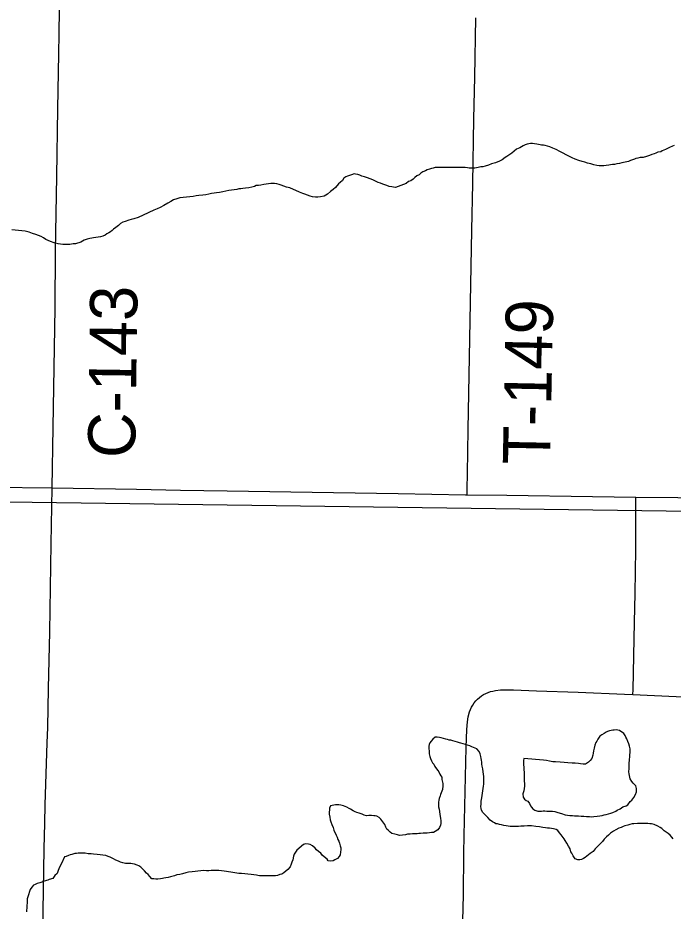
# Model space of a CAD drawing. Extents: x 2.1 to 73.9, y 4 to 26.
# Drawn here: x 46.07 to 46.463, y 19.554 to 20.091 of the extents above; entities that cross this region are included whole.
import ezdxf

# ---------------------------------------------------------------- set-up
doc = ezdxf.new("R2010")
doc.units = 0
for name, color, linetype in [('GM_X_County_Road', 7, 'Continuous'), ('GM_X_County_Road_Text', 7, 'Continuous'), ('GM_X_Minor_Lake', 7, 'Continuous'), ('GM_X_Minor_River', 7, 'Continuous'), ('GM_X_State_Route', 7, 'Continuous'), ('GM_X_Township_Road', 7, 'Continuous'), ('GM_X_Township_Road_Text', 7, 'Continuous')]:
    doc.layers.add(name, color=color, linetype=linetype)

msp = doc.modelspace()

# ---------------------------------------------------------------- linework, layer by layer
at = {"layer": 'GM_X_County_Road'}
for points in [[(46.09468, 20.06932), (46.0949, 20.08134), (46.09523, 20.11081), (46.09615, 20.14974), (46.09689, 20.1833)], [(46.09063, 19.80873), (46.09126, 19.84507), (46.09233, 19.91657), (46.09258, 19.95078), (46.09351, 19.99585), (46.09409, 20.03627), (46.09468, 20.06932)], [(46.33705, 19.54086), (46.33751, 19.56417), (46.33781, 19.58903), (46.33795, 19.5999), (46.33857, 19.6263), (46.33907, 19.65272), (46.33953, 19.66357), (46.33992, 19.66818), (46.34042, 19.6712), (46.34124, 19.67414), (46.34179, 19.67556), (46.34243, 19.67694), (46.34316, 19.67826), (46.344, 19.67953), (46.34494, 19.68071), (46.34598, 19.68182), (46.3471, 19.68283), (46.34831, 19.68374), (46.34959, 19.68453), (46.35095, 19.68521), (46.35235, 19.68581), (46.35379, 19.6863), (46.35526, 19.68669), (46.35675, 19.68699), (46.3598, 19.68735), (46.36287, 19.68749), (46.36751, 19.68747), (46.38148, 19.68688), (46.40633, 19.68595), (46.43427, 19.68478), (46.43929, 19.68457)], [(46.43929, 19.68457), (46.46532, 19.68344), (46.49326, 19.68214), (46.49798, 19.68199), (46.50147, 19.6819), (46.5063, 19.68176)]]:
    msp.add_lwpolyline(points, dxfattribs=at)
at = {"layer": 'GM_X_Minor_Lake'}
for points in [[(46.37385, 19.64611), (46.37366, 19.64497), (46.37366, 19.64364), (46.37366, 19.64231), (46.37384, 19.64098), (46.37402, 19.63642), (46.37402, 19.63262), (46.3742, 19.6311), (46.3742, 19.62958), (46.37381, 19.62673), (46.37324, 19.62483), (46.37343, 19.62293), (46.37418, 19.62178), (46.37513, 19.62083), (46.37627, 19.62045), (46.37722, 19.61911), (46.37779, 19.61778), (46.37836, 19.61683), (46.37912, 19.61588), (46.38044, 19.61511), (46.38216, 19.61454), (46.3833, 19.61454), (46.38444, 19.61453), (46.38539, 19.61472), (46.38634, 19.61472), (46.38767, 19.61452), (46.38938, 19.61452), (46.3909, 19.61451), (46.39242, 19.61432), (46.39413, 19.61374), (46.39641, 19.61317), (46.39869, 19.6124), (46.40135, 19.61201), (46.40307, 19.61182), (46.40421, 19.61181), (46.40535, 19.61181), (46.40668, 19.61162), (46.4082, 19.61161), (46.40972, 19.61142), (46.41143, 19.61141), (46.41314, 19.61122), (46.41428, 19.61121), (46.4158, 19.6114), (46.41789, 19.61158), (46.41942, 19.61177), (46.42075, 19.61196), (46.42208, 19.61233), (46.42322, 19.61252), (46.42607, 19.61327), (46.42722, 19.61365), (46.42893, 19.61459), (46.42988, 19.61516), (46.43159, 19.61592), (46.43331, 19.61705), (46.43521, 19.61781), (46.43616, 19.61837), (46.43769, 19.62027), (46.43864, 19.62103), (46.43978, 19.62273), (46.44074, 19.62444), (46.4415, 19.62615), (46.44151, 19.62805), (46.44094, 19.62976), (46.43942, 19.63129), (46.43866, 19.63224), (46.43771, 19.63395), (46.43734, 19.6349), (46.43715, 19.63586), (46.43696, 19.637), (46.43677, 19.63814), (46.43697, 19.64023), (46.43697, 19.64175), (46.43697, 19.64327), (46.43717, 19.64517), (46.43736, 19.64764), (46.43756, 19.65049), (46.43756, 19.65201), (46.43718, 19.65353), (46.43681, 19.65505), (46.43624, 19.65638), (46.43567, 19.6579), (46.4351, 19.65905), (46.43454, 19.66), (46.43378, 19.66114), (46.43112, 19.66305), (46.42922, 19.66343), (46.42808, 19.66325), (46.42713, 19.66325), (46.42522, 19.66269), (46.42408, 19.66231), (46.42313, 19.66193), (46.42199, 19.66118), (46.42066, 19.66042), (46.41932, 19.65947), (46.41818, 19.65777), (46.41761, 19.65663), (46.41703, 19.65568), (46.41646, 19.65416), (46.41608, 19.65245), (46.41569, 19.65074), (46.41531, 19.64941)], [(46.41531, 19.64941), (46.41512, 19.64808), (46.41454, 19.64618), (46.41359, 19.64486), (46.41264, 19.64391), (46.41073, 19.64277), (46.4094, 19.64278), (46.40788, 19.64297), (46.40655, 19.64317), (46.40465, 19.64336), (46.40275, 19.64337), (46.40028, 19.64356), (46.398, 19.64376), (46.39552, 19.64396), (46.39286, 19.64416), (46.39115, 19.64416), (46.38925, 19.64455), (46.38735, 19.64493), (46.38564, 19.64513), (46.37385, 19.64611)]]:
    msp.add_lwpolyline(points, dxfattribs=at)
at = {"layer": 'GM_X_Minor_River'}
for points in [[(46.45195, 20.00929), (46.45062, 20.00891), (46.44929, 20.00834), (46.44739, 20.00778), (46.44548, 20.00721), (46.44358, 20.00703), (46.44225, 20.00665), (46.44111, 20.00647), (46.44016, 20.00609), (46.43902, 20.00571), (46.43788, 20.00534), (46.43654, 20.00477), (46.43255, 20.00383), (46.43122, 20.00345), (46.4297, 20.00327), (46.42817, 20.00289), (46.42703, 20.0029), (46.42589, 20.00271), (46.42475, 20.00252), (46.42323, 20.00234), (46.42171, 20.00215), (46.42038, 20.00216), (46.41905, 20.00216), (46.41753, 20.00235), (46.41582, 20.00274), (46.41392, 20.00331), (46.41201, 20.0037), (46.4103, 20.00427), (46.40878, 20.00466), (46.40688, 20.00524), (46.4046, 20.00619), (46.40289, 20.00696), (46.40118, 20.00772), (46.39929, 20.00868), (46.39739, 20.00963), (46.3953, 20.01078), (46.39321, 20.01193), (46.39112, 20.01269), (46.38941, 20.01346), (46.38789, 20.01384), (46.38656, 20.01423), (46.38561, 20.01461), (46.38447, 20.01461), (46.38352, 20.01481), (46.38162, 20.01519), (46.38028, 20.01539), (46.37895, 20.01558), (46.37781, 20.01558), (46.37686, 20.0154), (46.37572, 20.01502), (46.37458, 20.01464), (46.37344, 20.01408), (46.3723, 20.01351), (46.37134, 20.01294), (46.37039, 20.01256), (46.36944, 20.01219), (46.36658, 20.00972), (46.36487, 20.00859), (46.36354, 20.00764), (46.36259, 20.00707), (46.36087, 20.00575), (46.35916, 20.00499), (46.35669, 20.00386), (46.3544, 20.0033), (46.3525, 20.00254), (46.3506, 20.00198), (46.34908, 20.0016), (46.34794, 20.00141), (46.34641, 20.00104), (46.34546, 20.00085), (46.34432, 20.00066), (46.34318, 20.00067), (46.34204, 20.00067), (46.3409, 20.00067), (46.33995, 20.00087), (46.33862, 20.00106), (46.33672, 20.00107), (46.3352, 20.00107), (46.33348, 20.00108), (46.33234, 20.00108), (46.33101, 20.00108), (46.32968, 20.00109), (46.32816, 20.00109), (46.32702, 20.00109), (46.32569, 20.0011), (46.32417, 20.0011), (46.32284, 20.00111), (46.32151, 20.00111), (46.32056, 20.00111), (46.31941, 20.00074), (46.31827, 20.00055), (46.31713, 20.00017), (46.3158, 19.9998), (46.31466, 19.99904), (46.31314, 19.99847), (46.31199, 19.99772), (46.31085, 19.99677), (46.30952, 19.99601), (46.30838, 19.99506), (46.30742, 19.99412), (46.3059, 19.99317)], [(46.46394, 20.01438), (46.46299, 20.01401), (46.46128, 20.01306), (46.46033, 20.01268), (46.4588, 20.01193), (46.45785, 20.01155), (46.4569, 20.01117), (46.45595, 20.01061), (46.45424, 20.01023), (46.4531, 20.00966), (46.45195, 20.00929)], [(46.3059, 19.99317), (46.30457, 19.99261), (46.30305, 19.99147), (46.29677, 19.98902), (46.29544, 19.98921), (46.29448, 19.9894), (46.29296, 19.98979), (46.29144, 19.99036), (46.28917, 19.99113), (46.28764, 19.9917), (46.28632, 19.99209), (46.28441, 19.99304), (46.28308, 19.99362), (46.28157, 19.99438), (46.27986, 19.99496), (46.27814, 19.99553), (46.27662, 19.99592), (46.2753, 19.99649), (46.27416, 19.99687), (46.27282, 19.99707), (46.27187, 19.99726), (46.27035, 19.9967), (46.26902, 19.99632), (46.26788, 19.99594), (46.26693, 19.99556), (46.26578, 19.99462), (46.26483, 19.99329), (46.2635, 19.99215), (46.26255, 19.9912), (46.26064, 19.98912), (46.25931, 19.98798), (46.25778, 19.98666), (46.25588, 19.98514), (46.25398, 19.98382), (46.25169, 19.98344), (46.25017, 19.98326), (46.24865, 19.98326), (46.24694, 19.98346), (46.24542, 19.98384), (46.2439, 19.98442), (46.24238, 19.98499), (46.24105, 19.98556), (46.23915, 19.98633), (46.23326, 19.98882), (46.23136, 19.98939), (46.22965, 19.98997), (46.22813, 19.99054), (46.2268, 19.99093), (46.22547, 19.99131), (46.22414, 19.9915), (46.223, 19.99151), (46.22186, 19.99151), (46.22053, 19.99133), (46.21919, 19.99114), (46.21767, 19.99095), (46.21596, 19.99058), (46.21444, 19.99039), (46.21311, 19.99021), (46.21216, 19.98964), (46.21044, 19.98926), (46.20873, 19.98889), (46.20664, 19.9887), (46.20512, 19.98852), (46.20379, 19.98833), (46.20265, 19.98834), (46.20151, 19.98796), (46.1998, 19.98777), (46.19827, 19.98759), (46.19675, 19.98721), (46.19485, 19.98684), (46.19314, 19.98646), (46.19105, 19.98609), (46.18933, 19.9859), (46.18781, 19.98572), (46.18629, 19.98553), (46.18458, 19.98516), (46.18287, 19.98478), (46.18116, 19.98441), (46.17868, 19.98422), (46.17716, 19.98404), (46.17526, 19.98366), (46.17336, 19.98348), (46.17127, 19.98329), (46.16917, 19.98311), (46.16727, 19.98292), (46.16537, 19.98236), (46.16347, 19.9816), (46.16176, 19.98066), (46.16004, 19.97971), (46.15757, 19.9782), (46.15547, 19.97707), (46.15357, 19.97631), (46.15167, 19.97555), (46.1452, 19.97253), (46.14215, 19.97102), (46.13968, 19.97027), (46.13797, 19.96989), (46.13664, 19.96952), (46.13435, 19.96876), (46.13302, 19.9682), (46.13169, 19.96744)], [(46.13169, 19.96744), (46.13035, 19.9663), (46.12883, 19.96498), (46.1275, 19.96403), (46.12655, 19.96327), (46.1256, 19.96252), (46.12464, 19.96195), (46.1235, 19.96119), (46.12236, 19.96043), (46.12103, 19.95987), (46.11969, 19.95949), (46.11817, 19.9593), (46.11684, 19.95912), (46.11551, 19.95893), (46.11437, 19.95875), (46.11323, 19.95837), (46.11171, 19.95799), (46.1098, 19.95743), (46.1079, 19.95629), (46.10467, 19.95535), (46.10314, 19.95517), (46.10219, 19.95498), (46.10124, 19.95479), (46.09991, 19.95479), (46.09839, 19.9548), (46.09706, 19.9548), (46.09554, 19.955), (46.09421, 19.95519), (46.09288, 19.95558), (46.09174, 19.95596), (46.08965, 19.95672), (46.08813, 19.9573), (46.0868, 19.95787), (46.08547, 19.95883), (46.08395, 19.95959), (46.08243, 19.96036), (46.08072, 19.96093), (46.07882, 19.96151), (46.07673, 19.96227), (46.07445, 19.96285), (46.06646, 19.96363)], [(45.71269, 19.80517), (46.5909, 19.79315)], [(46.36179, 19.60586), (46.36046, 19.60624), (46.35913, 19.60643), (46.35799, 19.60682), (46.35704, 19.60701), (46.35609, 19.60758), (46.35495, 19.60816), (46.35362, 19.60911), (46.35211, 19.61064), (46.35116, 19.61178), (46.35002, 19.61292), (46.34907, 19.61368), (46.34831, 19.61502), (46.34812, 19.61616), (46.34794, 19.6173), (46.34813, 19.61882), (46.34813, 19.62053), (46.34852, 19.62243), (46.34929, 19.62813), (46.34948, 19.62946), (46.34967, 19.63079), (46.34968, 19.6325), (46.34968, 19.63402), (46.34968, 19.63535), (46.3495, 19.63668), (46.34931, 19.6382), (46.34912, 19.63991), (46.34875, 19.64162), (46.34856, 19.64276), (46.34856, 19.6439), (46.34837, 19.64523), (46.34819, 19.64619), (46.348, 19.64733), (46.34762, 19.64904), (46.34705, 19.65037), (46.34553, 19.65189), (46.34364, 19.65285), (46.34249, 19.65323), (46.34136, 19.65381), (46.34003, 19.65419), (46.3387, 19.65458), (46.33737, 19.65496), (46.33603, 19.65534), (46.33508, 19.65554), (46.33394, 19.65592), (46.33261, 19.6563), (46.33109, 19.65669), (46.32995, 19.65707), (46.329, 19.65726), (46.32805, 19.65765), (46.32691, 19.65784), (46.32558, 19.65822), (46.32406, 19.65861), (46.32311, 19.6588), (46.32178, 19.659), (46.32064, 19.659), (46.31912, 19.65767), (46.31816, 19.65654), (46.3174, 19.65559), (46.31702, 19.65464), (46.31683, 19.6535), (46.31683, 19.65236), (46.31701, 19.65027), (46.31701, 19.64894), (46.31739, 19.64741), (46.31776, 19.64608), (46.31833, 19.64475), (46.3189, 19.64361), (46.31966, 19.64266), (46.32042, 19.64132), (46.32136, 19.63999), (46.32212, 19.63904), (46.32269, 19.63809), (46.32345, 19.63675), (46.32402, 19.6358), (46.32458, 19.63485), (46.32458, 19.63352), (46.32496, 19.632), (46.32515, 19.63105), (46.32514, 19.62972), (46.32495, 19.62763), (46.32457, 19.62649), (46.32419, 19.62554), (46.3238, 19.62459), (46.32361, 19.62364), (46.32304, 19.62212), (46.32285, 19.62117), (46.32265, 19.61984), (46.32265, 19.61832), (46.32265, 19.61718), (46.32302, 19.61566), (46.32321, 19.61433), (46.3234, 19.61243), (46.32378, 19.61034), (46.32396, 19.60863), (46.32396, 19.60711), (46.32377, 19.60616), (46.32319, 19.60464), (46.32205, 19.60331), (46.32053, 19.60237), (46.31957, 19.6018)], [(46.31957, 19.6018), (46.31843, 19.60161), (46.3171, 19.60142), (46.31577, 19.60124), (46.31444, 19.60124), (46.3133, 19.60125), (46.31178, 19.60106), (46.31083, 19.60106), (46.30969, 19.60088), (46.30855, 19.60088), (46.30702, 19.60088), (46.3055, 19.6007), (46.30398, 19.6007), (46.30265, 19.60033), (46.30094, 19.60014), (46.29923, 19.59996), (46.2979, 19.60034), (46.29638, 19.60072), (46.29448, 19.60111), (46.29353, 19.60187), (46.29258, 19.60283), (46.29163, 19.60378), (46.29087, 19.60492), (46.2903, 19.60644), (46.28803, 19.60968), (46.28689, 19.61063), (46.28556, 19.61159), (46.28461, 19.61178), (46.28366, 19.61178), (46.28233, 19.61198), (46.28081, 19.61198), (46.27928, 19.6118), (46.27795, 19.61218), (46.27682, 19.61275), (46.27491, 19.61333), (46.27359, 19.61371), (46.27245, 19.6141), (46.27131, 19.61467), (46.26979, 19.61562), (46.26884, 19.6162), (46.26751, 19.61696), (46.26656, 19.61734), (46.26542, 19.61773), (46.2639, 19.61811), (46.26276, 19.61831), (46.26181, 19.61831), (46.26067, 19.61831), (46.25971, 19.61812), (46.25876, 19.61794), (46.25781, 19.61775), (46.25705, 19.61642), (46.25705, 19.61528), (46.25685, 19.61395), (46.25685, 19.61262), (46.25723, 19.61091), (46.2576, 19.60939), (46.25798, 19.60806), (46.25855, 19.60653), (46.25931, 19.60463), (46.25968, 19.60311), (46.2612, 19.60007), (46.26177, 19.59892), (46.26214, 19.59759), (46.26271, 19.59645), (46.26309, 19.59531), (46.26347, 19.59379), (46.26385, 19.59246), (46.26384, 19.59151), (46.26365, 19.5898), (46.26346, 19.58828), (46.26288, 19.58733), (46.26193, 19.58619), (46.26041, 19.58524), (46.25927, 19.58468), (46.25774, 19.58449), (46.25622, 19.58469), (46.25565, 19.58564), (46.25395, 19.58716), (46.25281, 19.58812), (46.25186, 19.58926), (46.25053, 19.59021), (46.24939, 19.59136), (46.24844, 19.59231), (46.24692, 19.59365), (46.24541, 19.59441), (46.24446, 19.5946), (46.24274, 19.5948), (46.24141, 19.59442), (46.2376, 19.59101), (46.23665, 19.58987), (46.23589, 19.58874), (46.2355, 19.58741), (46.23512, 19.58532), (46.23455, 19.5838), (46.23416, 19.58266), (46.23359, 19.58114), (46.23207, 19.57944), (46.22978, 19.57754), (46.22845, 19.57678), (46.22731, 19.57641), (46.22597, 19.57584)], [(46.4635, 19.59796), (46.46255, 19.59891), (46.4616, 19.60005), (46.46046, 19.60101), (46.45914, 19.60196), (46.458, 19.60272), (46.45667, 19.60406), (46.45572, 19.60463), (46.4542, 19.60559), (46.45211, 19.60654), (46.4504, 19.60693), (46.44945, 19.60693), (46.44831, 19.60712), (46.44698, 19.60713), (46.44374, 19.60714), (46.44203, 19.60714), (46.43975, 19.60696), (46.4388, 19.60696), (46.43747, 19.60659), (46.43614, 19.60621), (46.43443, 19.60564), (46.43347, 19.60527), (46.43214, 19.6047), (46.43081, 19.60432), (46.4291, 19.60338), (46.42757, 19.60243), (46.42586, 19.6013), (46.42453, 19.60016), (46.42338, 19.59902), (46.42205, 19.5977), (46.42091, 19.59637), (46.41995, 19.59523), (46.419, 19.59429), (46.41786, 19.59315), (46.41652, 19.59182), (46.41538, 19.59031), (46.41367, 19.58917), (46.41252, 19.58822), (46.41157, 19.58747), (46.41062, 19.58671), (46.40967, 19.58614), (46.40834, 19.58539), (46.40738, 19.5852), (46.40624, 19.5852), (46.40453, 19.58597), (46.4034, 19.58768), (46.40264, 19.5892), (46.40207, 19.59015), (46.4015, 19.59187), (46.40056, 19.59358), (46.39961, 19.59529), (46.39866, 19.59682), (46.3979, 19.59796), (46.3962, 19.60024), (46.39525, 19.60158), (46.39411, 19.60291), (46.39316, 19.60348), (46.39164, 19.60387), (46.39031, 19.60406), (46.38917, 19.60426), (46.38803, 19.60426), (46.3867, 19.60445), (46.38518, 19.60465), (46.38328, 19.60503), (46.381, 19.60523), (46.37833, 19.60562), (46.37605, 19.60562), (46.37396, 19.60544), (46.37206, 19.60545), (46.37054, 19.60526), (46.36883, 19.60527), (46.36788, 19.60527), (46.36692, 19.60527), (46.3656, 19.60528), (46.36445, 19.60547), (46.36312, 19.60566), (46.36179, 19.60586)], [(46.22597, 19.57584), (46.22464, 19.57566), (46.22312, 19.57566), (46.2216, 19.57566), (46.22046, 19.57567), (46.21913, 19.57567), (46.21799, 19.57568), (46.21685, 19.57568), (46.21514, 19.57568), (46.21418, 19.57588), (46.21323, 19.57607), (46.21171, 19.57626), (46.21, 19.57646), (46.2081, 19.57665), (46.2062, 19.57685), (46.2043, 19.57705), (46.20278, 19.57705), (46.20145, 19.57724), (46.20031, 19.57744), (46.19898, 19.57763), (46.19784, 19.57782), (46.19651, 19.57802), (46.19518, 19.57821), (46.19384, 19.57841), (46.19232, 19.5786), (46.19061, 19.57879), (46.18928, 19.5788), (46.18776, 19.5788), (46.18605, 19.57881), (46.18472, 19.57862), (46.1832, 19.57863), (46.18149, 19.57882), (46.17996, 19.57864), (46.17464, 19.57808), (46.17255, 19.5779), (46.17084, 19.57752), (46.16893, 19.57696), (46.16722, 19.57658), (46.16551, 19.57621), (46.16399, 19.57564), (46.1617, 19.57508), (46.16018, 19.5747), (46.15885, 19.57452), (46.15771, 19.57433), (46.15676, 19.57414), (46.15562, 19.57395), (46.1541, 19.57377), (46.15276, 19.57377), (46.15162, 19.57378), (46.15048, 19.57397), (46.14916, 19.5753), (46.14821, 19.57645), (46.14726, 19.57721), (46.14612, 19.57873), (46.14479, 19.57988), (46.14384, 19.58083), (46.1427, 19.58159), (46.14156, 19.58217), (46.14004, 19.58274), (46.1389, 19.58293), (46.13776, 19.58313), (46.13662, 19.58313), (46.13567, 19.58313), (46.13472, 19.58314), (46.13301, 19.58352), (46.13168, 19.58391), (46.13035, 19.58448), (46.12883, 19.58505), (46.1275, 19.58582), (46.12655, 19.58639), (46.12541, 19.58696), (46.12427, 19.58735), (46.12275, 19.58792), (46.11762, 19.58851), (46.11553, 19.5887), (46.11401, 19.5889), (46.1123, 19.5889), (46.1104, 19.58929), (46.10888, 19.58929), (46.10773, 19.5893), (46.10621, 19.5893), (46.10526, 19.58911), (46.10431, 19.58912), (46.10241, 19.58855), (46.10146, 19.58836), (46.10051, 19.5878), (46.09898, 19.58723), (46.09803, 19.58704), (46.09631, 19.58306), (46.09498, 19.58097), (46.09421, 19.57888), (46.09364, 19.57717), (46.09231, 19.57585), (46.09097, 19.57414), (46.08888, 19.57339), (46.08793, 19.57301), (46.08583, 19.57245), (46.0845, 19.57188), (46.08317, 19.5715), (46.08165, 19.57113), (46.08032, 19.57056)], [(46.08032, 19.57056), (46.07936, 19.56999), (46.07841, 19.56886), (46.07746, 19.56753), (46.07593, 19.56297), (46.07554, 19.56183), (46.07554, 19.56012), (46.07534, 19.55727), (46.07515, 19.55404)]]:
    msp.add_lwpolyline(points, dxfattribs=at)
at = {"layer": 'GM_X_State_Route'}
for points in [[(45.17323, 19.82086), (45.22308, 19.82018), (45.25416, 19.8197), (45.28214, 19.81928), (45.32891, 19.8186), (45.35675, 19.81818), (45.43913, 19.81697), (45.52929, 19.81562), (45.5697, 19.81497), (45.58418, 19.8148), (45.61167, 19.81449), (45.66606, 19.81365), (45.72514, 19.81278), (45.78109, 19.81191), (45.85725, 19.81087), (45.88834, 19.81038), (45.91166, 19.81011), (45.95363, 19.80983), (46.01581, 19.80917), (46.05467, 19.80905), (46.09063, 19.80873)], [(46.08059, 19.30232), (46.08077, 19.30902), (46.08199, 19.3634), (46.08282, 19.41468), (46.08392, 19.4644), (46.08493, 19.52035), (46.08508, 19.53278), (46.0852, 19.55453), (46.08591, 19.59183), (46.08625, 19.60736), (46.08649, 19.61823), (46.08701, 19.63688), (46.08758, 19.65551), (46.08792, 19.66482), (46.08846, 19.68812), (46.08915, 19.72231), (46.08999, 19.77515), (46.09063, 19.80873)], [(46.09063, 19.80873), (46.14127, 19.80784), (46.16771, 19.80737), (46.1957, 19.80687), (46.25947, 19.80591), (46.29834, 19.80524), (46.33878, 19.80458), (46.33969, 19.80457)], [(46.33969, 19.80457), (46.36366, 19.80422), (46.41498, 19.80354), (46.44094, 19.80319)], [(46.44094, 19.80319), (46.4663, 19.80284), (46.49274, 19.80259), (46.5223, 19.80218), (46.54097, 19.80168), (46.54299, 19.80157)]]:
    msp.add_lwpolyline(points, dxfattribs=at)
at = {"layer": 'GM_X_Township_Road'}
for points in [[(46.33969, 19.80457), (46.33975, 19.80802), (46.33991, 19.81735), (46.34046, 19.84379), (46.3418, 19.92), (46.34256, 19.96355), (46.34312, 19.99153), (46.34383, 20.03042), (46.34431, 20.0553), (46.34506, 20.09107)], [(46.43929, 19.68457), (46.43937, 19.68748), (46.43988, 19.70774), (46.44031, 19.728), (46.4407, 19.74515), (46.44097, 19.77165), (46.44105, 19.79504), (46.44099, 19.79972), (46.44094, 19.80319)]]:
    msp.add_lwpolyline(points, dxfattribs=at)

# ---------------------------------------------------------------- texts
at = {"layer": 'GM_X_County_Road_Text'}
msp.add_text('C-143', height=0.028409, rotation=89.1736, dxfattribs=at).set_placement((46.14042, 19.82645))
at = {"layer": 'GM_X_Township_Road_Text'}
msp.add_text('T-149', height=0.028409, rotation=88.8768, dxfattribs=at).set_placement((46.38953, 19.82242))

doc.saveas('drawing.dxf')
